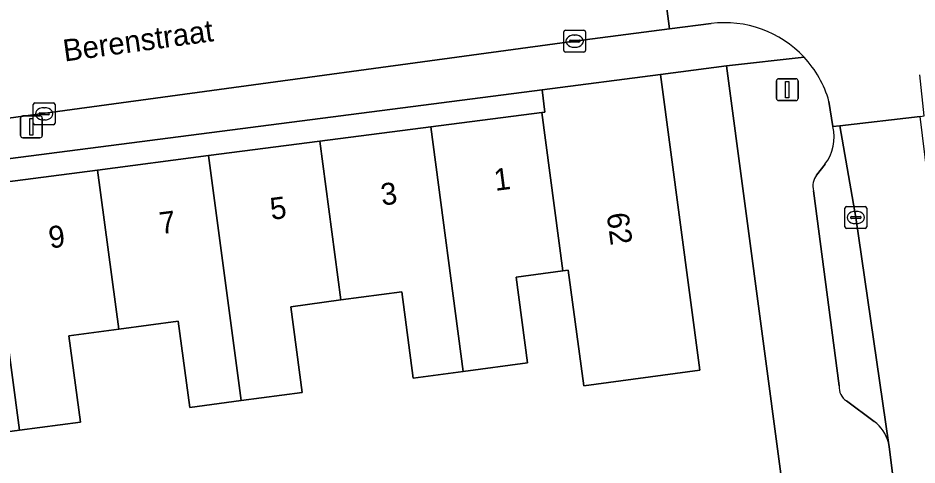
# Model space of a CAD drawing. Extents: x 163147 to 163550, y 380933 to 381639.
# Drawn here: x 163449.17 to 163490.26, y 381293.5 to 381313.94 of the extents above; entities that cross this region are included whole.
import ezdxf

# ---------------------------------------------------------------- set-up
doc = ezdxf.new("R2010")
doc.units = 0
for name, color, linetype in [('IMGEO_Erf', 7, 'Continuous'), ('IMGEO_Kolk', 7, 'Continuous'), ('IMGEO_Lichtmast', 7, 'Continuous'), ('IMGEO_Openbare_ruimte_label', 7, 'Continuous'), ('IMGEO_Pand', 7, 'Continuous'), ('IMGEO_Pand_nummerreeks', 7, 'Continuous'), ('IMGEO_Parkeervlak_open', 7, 'Continuous'), ('IMGEO_Rijbaan_lokaal_open', 7, 'Continuous'), ('IMGEO_Voetpad_open', 7, 'Continuous')]:
    doc.layers.add(name, color=color, linetype=linetype)

msp = doc.modelspace()

# ---------------------------------------------------------------- linework, layer by layer
at = {"layer": 'IMGEO_Erf'}
msp.add_lwpolyline([(163484.876, 381286.803), (163481.558, 381311.755), (163478.534, 381311.364), (163480.342, 381297.835), (163475.028, 381297.125), (163474.316, 381302.419), (163474.075, 381302.387), (163471.936, 381302.1), (163472.463, 381298.171), (163469.526, 381297.777), (163467.24, 381297.471), (163466.71, 381301.423), (163463.928, 381301.05), (163461.638, 381300.743), (163462.164, 381296.82), (163459.379, 381296.447), (163457.024, 381296.131), (163456.495, 381300.075), (163453.78, 381299.711), (163451.502, 381299.405), (163452.03, 381295.47), (163449.233, 381295.095), (163446.828, 381294.772)], dxfattribs=at)
msp.add_lwpolyline([(163432.643, 381305.427), (163432.775, 381304.402), (163437.582, 381305.024), (163442.658, 381305.68), (163447.734, 381306.336), (163452.809, 381306.992), (163457.886, 381307.649), (163462.961, 381308.305), (163468.036, 381308.961), (163473.112, 381309.617), (163473.258, 381309.636), (163473.125, 381310.664)], close=True, dxfattribs=at)
at = {"layer": 'IMGEO_Kolk'}
for p, q in [((163474.114, 381312.456), (163474.114, 381313.308)), ((163474.189, 381313.382), (163475.041, 381313.382)), ((163474.602, 381313.162), (163474.627, 381313.162)), ((163475.115, 381313.308), (163475.115, 381312.456)), ((163474.373, 381312.876), (163474.373, 381312.888)), ((163474.811, 381312.839), (163474.413, 381312.839)), ((163474.416, 381312.925), (163474.814, 381312.925)), ((163474.857, 381312.888), (163474.857, 381312.876)), ((163475.041, 381312.382), (163474.189, 381312.382)), ((163474.625, 381312.602), (163474.6, 381312.602)), ((163449.866, 381309.137), (163449.866, 381309.989)), ((163449.941, 381310.063), (163450.793, 381310.063)), ((163450.867, 381309.989), (163450.867, 381309.137)), ((163450.125, 381309.557), (163450.125, 381309.569)), ((163450.563, 381309.52), (163450.165, 381309.52)), ((163450.168, 381309.606), (163450.566, 381309.606)), ((163450.354, 381309.843), (163450.379, 381309.843)), ((163450.609, 381309.569), (163450.609, 381309.557)), ((163450.793, 381309.063), (163449.941, 381309.063)), ((163450.377, 381309.283), (163450.352, 381309.283)), ((163486.966, 381304.396), (163486.966, 381305.248)), ((163487.041, 381305.322), (163487.893, 381305.322)), ((163487.454, 381305.102), (163487.479, 381305.102)), ((163487.967, 381305.248), (163487.967, 381304.396)), ((163487.225, 381304.816), (163487.225, 381304.828)), ((163487.663, 381304.779), (163487.265, 381304.779)), ((163487.268, 381304.865), (163487.666, 381304.865)), ((163487.477, 381304.542), (163487.452, 381304.542)), ((163487.709, 381304.828), (163487.709, 381304.816)), ((163487.893, 381304.322), (163487.041, 381304.322))]:
    msp.add_line(p, q, dxfattribs=at)
for points in [[(163474.114, 381312.456), (163474.114, 381313.308)], [(163474.189, 381313.382), (163475.041, 381313.382)], [(163475.115, 381313.308), (163475.115, 381312.456)], [(163475.041, 381312.382), (163474.189, 381312.382)], [(163449.866, 381309.137), (163449.866, 381309.989)], [(163449.941, 381310.063), (163450.793, 381310.063)], [(163450.867, 381309.989), (163450.867, 381309.137)], [(163450.793, 381309.063), (163449.941, 381309.063)], [(163486.966, 381304.396), (163486.966, 381305.248)], [(163487.041, 381305.322), (163487.893, 381305.322)], [(163487.967, 381305.248), (163487.967, 381304.396)], [(163487.893, 381304.322), (163487.041, 381304.322)]]:
    msp.add_lwpolyline(points, dxfattribs=at)
for centre, radius, start, end in [((163474.191, 381313.306), 0.0765, 91.552, 178.448), ((163474.191, 381313.306), 0.0765, 91.552, 178.448), ((163475.039, 381313.306), 0.0765, 1.552, 88.448), ((163475.039, 381313.306), 0.0765, 1.552, 88.448), ((163474.413, 381312.885), 0.0403, 85.8775, 175.7526), ((163474.41, 381312.875), 0.0366, 178.938, 274.7102), ((163474.814, 381312.882), 0.043, 264.8664, 352.4533), ((163474.818, 381312.887), 0.0386, 1.7309, 96.639), ((163474.191, 381312.458), 0.0765, 181.552, 268.448), ((163474.191, 381312.458), 0.0765, 181.552, 268.448), ((163475.039, 381312.458), 0.0765, 271.552, 358.448), ((163475.039, 381312.458), 0.0765, 271.552, 358.448), ((163449.943, 381309.987), 0.0765, 91.552, 178.448), ((163449.943, 381309.987), 0.0765, 91.552, 178.448), ((163450.791, 381309.987), 0.0765, 1.552, 88.448), ((163450.791, 381309.987), 0.0765, 1.552, 88.448), ((163450.165, 381309.566), 0.0403, 85.8775, 175.7526), ((163450.162, 381309.556), 0.0366, 178.938, 274.7102), ((163450.566, 381309.563), 0.043, 264.8664, 352.4533), ((163450.57, 381309.568), 0.0386, 1.7309, 96.639), ((163449.943, 381309.139), 0.0765, 181.552, 268.448), ((163449.943, 381309.139), 0.0765, 181.552, 268.448), ((163450.791, 381309.139), 0.0765, 271.552, 358.448), ((163450.791, 381309.139), 0.0765, 271.552, 358.448), ((163487.043, 381305.246), 0.0765, 91.552, 178.448), ((163487.043, 381305.246), 0.0765, 91.552, 178.448), ((163487.891, 381305.246), 0.0765, 1.552, 88.448), ((163487.891, 381305.246), 0.0765, 1.552, 88.448), ((163487.265, 381304.825), 0.0403, 85.8775, 175.7526), ((163487.262, 381304.815), 0.0366, 178.938, 274.7102), ((163487.666, 381304.822), 0.043, 264.8664, 352.4533), ((163487.67, 381304.827), 0.0386, 1.7309, 96.639), ((163487.043, 381304.398), 0.0765, 181.552, 268.448), ((163487.043, 381304.398), 0.0765, 181.552, 268.448), ((163487.891, 381304.398), 0.0765, 271.552, 358.448), ((163487.891, 381304.398), 0.0765, 271.552, 358.448)]:
    msp.add_arc(centre, radius, start, end, dxfattribs=at)
for centre, major_axis, ratio, start_param, end_param in [((163474.601, 381312.882), (-0.387, 0.002), 0.722429, 4.712389, 7.853982), ((163474.626, 381312.882), (-0.39, 0.002), 0.717154, 1.570796, 4.712389), ((163450.353, 381309.563), (-0.387, 0.002), 0.722429, 4.712389, 7.853982), ((163450.378, 381309.563), (-0.39, 0.002), 0.717154, 1.570796, 4.712389), ((163487.453, 381304.822), (-0.387, 0.002), 0.722429, 4.712389, 7.853982), ((163487.478, 381304.822), (-0.39, 0.002), 0.717154, 1.570796, 4.712389)]:
    msp.add_ellipse(centre, major_axis=major_axis, ratio=ratio, start_param=start_param, end_param=end_param, dxfattribs=at)
at = {"layer": 'IMGEO_Lichtmast'}
for p, q in [((163483.935, 381311.165), (163484.725, 381311.165)), ((163484.725, 381311.165), (163483.935, 381311.165)), ((163483.835, 381310.265), (163483.835, 381311.065)), ((163483.835, 381311.065), (163483.835, 381310.265)), ((163484.825, 381311.065), (163484.825, 381310.265)), ((163484.825, 381310.265), (163484.825, 381311.065)), ((163484.725, 381310.165), (163483.935, 381310.165)), ((163483.935, 381310.165), (163484.725, 381310.165)), ((163449.386, 381309.466), (163450.176, 381309.466)), ((163450.176, 381309.466), (163449.386, 381309.466)), ((163449.286, 381308.566), (163449.286, 381309.366)), ((163449.286, 381309.366), (163449.286, 381308.566)), ((163450.276, 381309.366), (163450.276, 381308.566)), ((163450.276, 381308.566), (163450.276, 381309.366)), ((163450.176, 381308.466), (163449.386, 381308.466)), ((163449.386, 381308.466), (163450.176, 381308.466))]:
    msp.add_line(p, q, dxfattribs=at)
for points in [[(163484.255, 381311.04), (163484.405, 381311.04), (163484.405, 381310.29), (163484.255, 381310.29), (163484.255, 381311.04)], [(163449.706, 381309.341), (163449.856, 381309.341), (163449.856, 381308.591), (163449.706, 381308.591), (163449.706, 381309.341)]]:
    msp.add_lwpolyline(points, dxfattribs=at)
for centre, start, end in [((163483.935, 381311.065), 90, 180), ((163483.935, 381311.065), 90, 180), ((163484.725, 381311.065), 0, 90), ((163484.725, 381311.065), 360, 90), ((163483.935, 381310.265), 180, 270), ((163483.935, 381310.265), 180, 270), ((163484.725, 381310.265), 270, 0), ((163484.725, 381310.265), 270, 0), ((163449.386, 381309.366), 90, 180), ((163449.386, 381309.366), 90, 180), ((163450.176, 381309.366), 0, 90), ((163450.176, 381309.366), 360, 90), ((163449.386, 381308.566), 180, 270), ((163449.386, 381308.566), 180, 270), ((163450.176, 381308.566), 270, 0), ((163450.176, 381308.566), 270, 0)]:
    msp.add_arc(centre, 0.1, start, end, dxfattribs=at)
at = {"layer": 'IMGEO_Pand'}
for points in [[(163473.112, 381309.617), (163474.075, 381302.387), (163474.316, 381302.419), (163475.028, 381297.125), (163480.342, 381297.835), (163478.534, 381311.364), (163473.125, 381310.664), (163473.258, 381309.636)], [(163473.112, 381309.617), (163468.036, 381308.961), (163469.526, 381297.777), (163472.463, 381298.171), (163471.936, 381302.1), (163474.075, 381302.387)], [(163463.928, 381301.05), (163466.71, 381301.423), (163467.24, 381297.471), (163469.526, 381297.777), (163468.036, 381308.961), (163462.961, 381308.305)], [(163457.886, 381307.649), (163459.379, 381296.447), (163462.164, 381296.82), (163461.638, 381300.743), (163463.928, 381301.05), (163462.961, 381308.305)], [(163457.886, 381307.649), (163452.809, 381306.992), (163453.78, 381299.711), (163456.495, 381300.075), (163457.024, 381296.131), (163459.379, 381296.447)], [(163447.734, 381306.336), (163449.233, 381295.095), (163452.03, 381295.47), (163451.502, 381299.405), (163453.78, 381299.711), (163452.809, 381306.992)], [(163447.734, 381306.336), (163442.658, 381305.68), (163443.636, 381298.348), (163446.3, 381298.705), (163446.828, 381294.772), (163449.233, 381295.095)]]:
    msp.add_lwpolyline(points, close=True, dxfattribs=at)
at = {"layer": 'IMGEO_Parkeervlak_open'}
for points in [[(163488.958, 381294.533), (163487.468, 381304.821), (163486.73, 381309.012), (163486.415, 381308.977)], [(163486.058, 381307.255), (163485.676, 381306.763)], [(163485.536, 381306.044), (163486.711, 381297.124)], [(163487.037, 381296.437), (163488.311, 381295.492)]]:
    msp.add_lwpolyline(points, dxfattribs=at)
for centre, radius, start, end in [((163484.387, 381308.499), 2.083, 323.3229, 13.2522), ((163486.279, 381306.272), 0.777, 140.8729, 197.0901), ((163487.414, 381297.037), 0.708, 172.9172, 237.854), ((163487.227, 381294.063), 1.794, 15.1929, 52.8191)]:
    msp.add_arc(centre, radius, start, end, dxfattribs=at)
at = {"layer": 'IMGEO_Rijbaan_lokaal_open'}
for points in [[(163479.082, 381319.899), (163478.118, 381319.785), (163478.14, 381319.616), (163478.952, 381313.454), (163480.848, 381313.687)], [(163486.239, 381310.132), (163486.415, 381308.977), (163486.73, 381309.012), (163490.402, 381309.443), (163490.584, 381309.465), (163490.394, 381311.344)]]:
    msp.add_lwpolyline(points, dxfattribs=at)
for points in [[(163478.952, 381313.454), (163478.14, 381319.616), (163422.756, 381312.154), (163422.382, 381312.104), (163422.173, 381312.093), (163422.932, 381305.852), (163423.08, 381305.875), (163472.145, 381312.545), (163474.614, 381312.883)], [(163494.08, 381255.92), (163497.43, 381256.373), (163496.541, 381263.222), (163493.759, 381284.035), (163490.846, 381305.849), (163490.402, 381309.443), (163486.73, 381309.012), (163487.468, 381304.821), (163488.958, 381294.533), (163488.987, 381294.337), (163489.02, 381294.106), (163490.135, 381285.185), (163490.149, 381285.047), (163490.358, 381282.994), (163493.013, 381263.045)]]:
    msp.add_lwpolyline(points, close=True, dxfattribs=at)
for centre, radius, start, end in [((163481.478, 381308.776), 4.951, 43.0173, 97.3134), ((163481.488, 381308.784), 4.939, 15.8417, 43.0298)]:
    msp.add_arc(centre, radius, start, end, dxfattribs=at)
at = {"layer": 'IMGEO_Voetpad_open'}
for points in [[(163480.848, 381313.687), (163478.952, 381313.454), (163474.614, 381312.883), (163472.145, 381312.545), (163423.08, 381305.875), (163422.932, 381305.852)], [(163485.098, 381312.154), (163481.558, 381311.755), (163484.876, 381286.803)], [(163481.558, 381311.755), (163485.098, 381312.154)], [(163420.06, 381303.821), (163421.926, 381304.051), (163427.187, 381304.722), (163427.294, 381304.736), (163432.37, 381305.392), (163432.643, 381305.427), (163473.125, 381310.664), (163478.534, 381311.364), (163481.558, 381311.755)], [(163486.415, 381308.977), (163486.239, 381310.132)], [(163485.676, 381306.763), (163486.058, 381307.255)], [(163486.711, 381297.124), (163485.536, 381306.044)], [(163488.311, 381295.492), (163487.037, 381296.437)], [(163490.149, 381285.047), (163490.135, 381285.185), (163489.02, 381294.106), (163488.987, 381294.337), (163488.958, 381294.533)]]:
    msp.add_lwpolyline(points, dxfattribs=at)
for centre, radius, start, end in [((163481.478, 381308.776), 4.951, 43.0173, 97.3134), ((163481.488, 381308.784), 4.939, 15.8417, 43.0298), ((163484.387, 381308.499), 2.083, 323.3229, 13.2522), ((163486.279, 381306.272), 0.777, 140.8729, 197.0901), ((163487.414, 381297.037), 0.708, 172.9172, 237.854), ((163487.227, 381294.063), 1.794, 15.1929, 52.8191)]:
    msp.add_arc(centre, radius, start, end, dxfattribs=at)

# ---------------------------------------------------------------- texts
at = {"layer": 'IMGEO_Openbare_ruimte_label'}
msp.add_text('Berenstraat', height=1, rotation=7.8142, dxfattribs=at).set_placement((163451.301, 381311.949))
at = {"layer": 'IMGEO_Pand_nummerreeks'}
for s, rotation, p in [('1', 7.3668, (163470.989, 381306.035)), ('3', 7.3668, (163465.815, 381305.366)), ('5', 7.3668, (163460.755, 381304.711)), ('7', 7.3668, (163455.695, 381304.057)), ('62', 277.6118, (163476.077, 381304.986)), ('9', 7.3668, (163450.634, 381303.403))]:
    msp.add_text(s, height=1, rotation=rotation, dxfattribs=at).set_placement(p)

doc.saveas('drawing.dxf')
